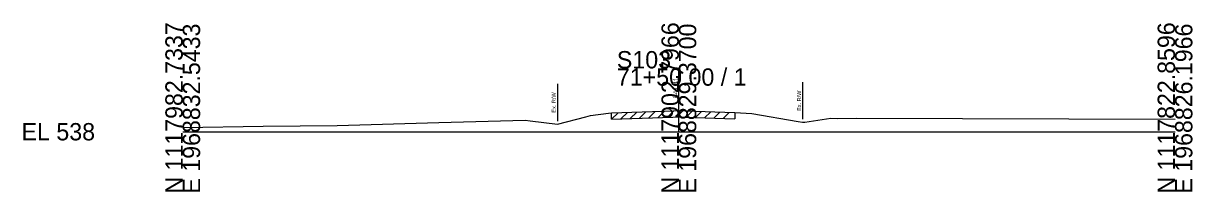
# Model space of a CAD drawing. Extents: x -26 to 163, y -10 to 24018.
# Drawn here: x -25.7 to 162.8, y 19490.3 to 19517.5 of the extents above; entities that cross this region are included whole.
import ezdxf

# ---------------------------------------------------------------- set-up
doc = ezdxf.new("R2010")
doc.units = 0
for name, color, linetype in [('RD_GPK_XS_Cell', 7, 'Continuous'), ('RD_XS_ExGround', 7, 'Continuous'), ('RD_XS_ExPaveRet', 7, 'Continuous'), ('RD_XS_ExRW', 7, 'Continuous'), ('RD_XS_TX_Elev_EX', 7, 'Continuous')]:
    doc.layers.add(name, color=color, linetype=linetype)

msp = doc.modelspace()

# ---------------------------------------------------------------- linework, layer by layer
at = {"layer": 'RD_GPK_XS_Cell'}
for p, q in [((80, 19500), (80, 19510.24)), ((0, 19500), (80, 19500)), ((80, 19500), (160, 19500))]:
    msp.add_line(p, q, dxfattribs=at)
at = {"layer": 'RD_XS_ExGround'}
msp.add_lwpolyline([(0, 19500.67), (12.96, 19500.89), (24.91, 19501.02), (41.3, 19501.48), (55.24, 19501.88), (56.02, 19501.77), (60.41, 19501.23), (65, 19502.41), (65.75, 19502.6), (68.67, 19502.98), (69.16, 19503.04), (79.02, 19503.38), (80.14, 19503.41), (81.04, 19503.38), (89.01, 19503.09), (91.77, 19502.96), (99.26, 19501.64), (99.96, 19501.52), (100.32, 19501.57), (104.53, 19502.17), (105.63, 19502.12), (108.59, 19502.18), (160, 19502.01)], dxfattribs=at)
at = {"layer": 'RD_XS_ExPaveRet'}
for p, q in [((69.16, 19502.04), (70.2, 19503.08)), ((69.16, 19502.04), (69.16, 19503.04)), ((69.16, 19502.04), (79.02, 19502.38)), ((70.66, 19502.09), (71.7, 19503.13)), ((72.16, 19502.15), (73.2, 19503.18)), ((73.66, 19502.2), (74.7, 19503.23)), ((75.16, 19502.25), (76.2, 19503.28)), ((76.66, 19502.3), (77.7, 19503.33)), ((78.16, 19502.35), (79.2, 19503.38)), ((79.02, 19502.38), (80.14, 19502.41)), ((79.66, 19502.4), (80.66, 19503.4)), ((80.14, 19502.41), (81.04, 19502.38)), ((81.04, 19502.38), (89.01, 19502.09)), ((81.16, 19502.38), (82.13, 19503.34)), ((82.66, 19502.32), (83.63, 19503.29)), ((84.16, 19502.27), (85.13, 19503.23)), ((85.66, 19502.21), (86.63, 19503.18)), ((87.16, 19502.16), (88.13, 19503.12)), ((89.01, 19503.09), (89.01, 19502.09))]:
    msp.add_line(p, q, dxfattribs=at)
at = {"layer": 'RD_XS_ExRW'}
for p, q in [((60.41, 19507.73), (60.41, 19501.73)), ((99.96, 19508.02), (99.96, 19502.02))]:
    msp.add_line(p, q, dxfattribs=at)

# ---------------------------------------------------------------- texts
at = {"layer": 'RD_GPK_XS_Cell'}
for s, p in [('N 1117982.7337', (0, 19490)), ('E 1968832.5433', (2.8, 19490)), ('N 1117902.7966', (80, 19490)), ('E 1968829.3700', (82.8, 19490)), ('N 1117822.8596', (160, 19490)), ('E 1968826.1966', (162.8, 19490))]:
    msp.add_text(s, height=2.8, rotation=90, dxfattribs=at).set_placement(p)
for s, p in [('S103', (70, 19510.24)), ('71+50.00 / 1', (70, 19507.44)), ('EL 538', (-26, 19498.6))]:
    msp.add_text(s, height=2.8, dxfattribs=at).set_placement(p)
at = {"layer": 'RD_XS_ExRW'}
for p in [(60.16, 19503.08), (99.71, 19503.36)]:
    msp.add_text('Ex. R/W ', height=0.65, rotation=90, dxfattribs=at).set_placement(p)
at = {"layer": 'RD_XS_TX_Elev_EX'}
msp.add_text('541.41', height=0.8, rotation=90, dxfattribs=at).set_placement((79.9, 19505.41))

doc.saveas('drawing.dxf')
